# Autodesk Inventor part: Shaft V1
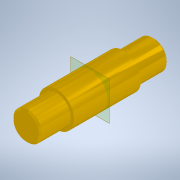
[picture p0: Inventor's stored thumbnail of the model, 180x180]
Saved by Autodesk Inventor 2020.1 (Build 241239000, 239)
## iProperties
Created: 2018-06
Part Number: Shaft V1
Material: Iron, Cast
Document SubType Name: Modeling
Designer: Power User
Density: 7.15 g/cm^3
Appearance: Aluminum - Polished(3)
Mass: 182.904 g
Surface Area: 57.4309 cm^2
Volume: 25.5809 cm^3
Author: Power User
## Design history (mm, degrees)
sketch "Sketch1"
  geometry: C1 r 9 at (0, 0); C2 r 11 at (0, 0); 1 further point
  constraints: 2 centre point, 2 coincident
  dimensions: "d0" = 18 diameter of C1; "d1" = 22 diameter of C2
extrude "Extrusion1" new body sketch "Sketch1" stored distance "d2" = 80; taper "d3" = 0 deg
extrude "Extrusion2" join sketch "Sketch1" stored distance "d4" = 42; taper "d5" = 0 deg
chamfer "Chamfer1" distance "d6" = 1; stored, may be unused: second distance "d7" = 2, angle "d8" = 45 deg
chamfer "Chamfer2" distance "d9" = 1; stored, may be unused: second distance "d10" = 2, angle "d11" = 45 deg
workplane "Work Plane1"
sketch "Sketch2"
  geometry: C1 r 8 at (0, 0) reference; 2 further points
  constraints: 1 coincident
hole "Hole1" sketch "Sketch2" at (0, 0) diameter "d12" = 6; stored, may be unused: countersink angle "d16" = 90 deg, drill point angle "d18" = 118 deg; dims "d13" = 6, "d14" = 8, "d15" = 5, "d17" = 25
body "Solid1"
